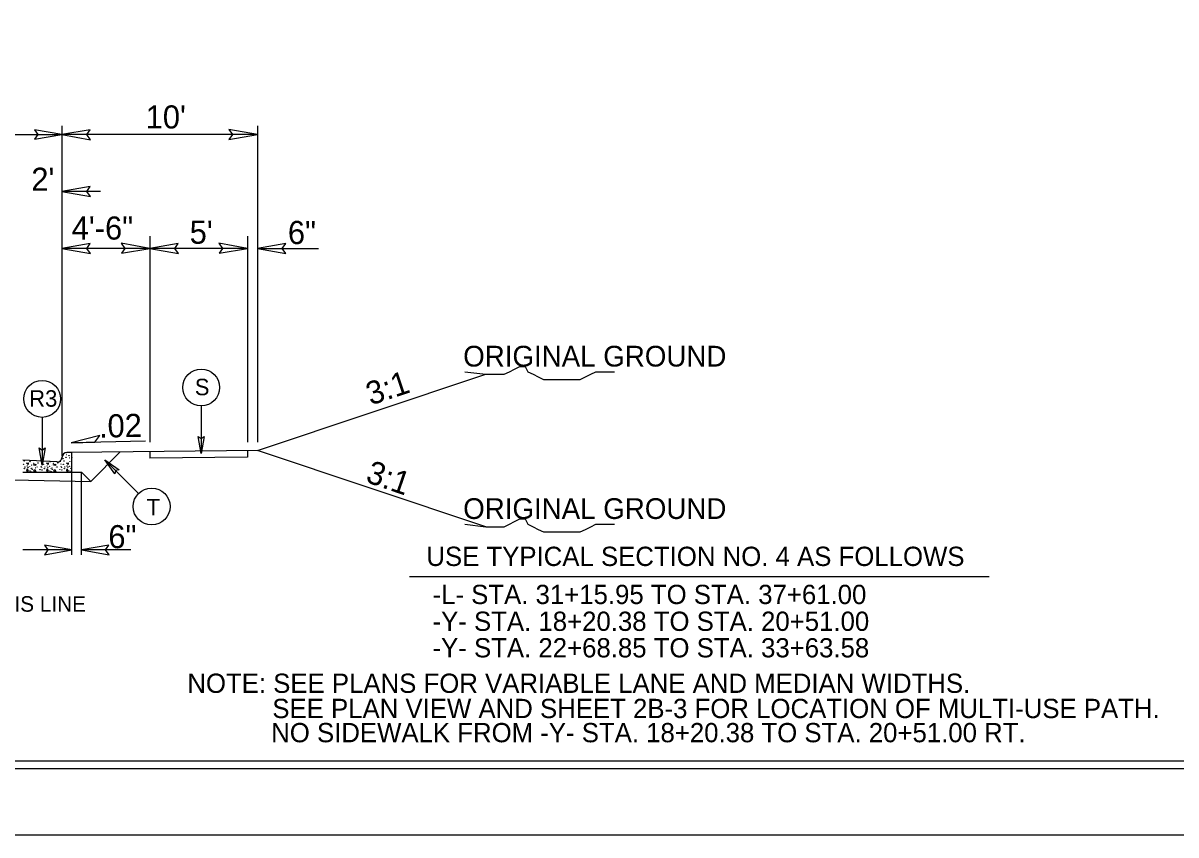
# Model space of a CAD drawing. Extents: x 958711 to 962106, y 831169 to 840840.
# Drawn here: x 959766.7 to 960156.3, y 838515.4 to 838789.5 of the extents above; entities that cross this region are included whole.
import ezdxf

# ---------------------------------------------------------------- set-up
doc = ezdxf.new("R2010")
doc.units = 0
for name, color, linetype in [('Old_Level_1', 7, 'Continuous'), ('Old_Level_11', 7, 'Continuous'), ('Old_Level_21', 7, 'Continuous'), ('Old_Level_3', 7, 'Continuous'), ('Prop Dimension Text', 7, 'Continuous'), ('Sheet Plot Border Inside CELL', 7, 'Continuous'), ('Sheet Plot Border Outside CELL', 7, 'Continuous'), ('Sheet Typical CELL', 7, 'Continuous'), ('Typical ID Circle CELL', 7, 'Continuous'), ('Typical Terminator CELL', 7, 'Continuous'), ('Typical Text ID Circle CELL', 7, 'Continuous')]:
    doc.layers.add(name, color=color, linetype=linetype)

msp = doc.modelspace()

# ---------------------------------------------------------------- linework, layer by layer
at = {"layer": 'Old_Level_1'}
for p, q in [((959779.86, 838754.86), (959779.86, 838643.28)), ((959845.9, 838754.86), (959845.9, 838648.04)), ((959213.41, 838751.85), (959779.86, 838751.85)), ((959845.9, 838751.85), (959779.86, 838751.85)), ((959792.92, 838732.63), (959779.86, 838732.63)), ((959809.57, 838717.61), (959809.57, 838648.04)), ((959842.59, 838717.61), (959842.59, 838648.04)), ((959809.57, 838713.44), (959779.86, 838713.44)), ((959842.59, 838713.44), (959809.57, 838713.44)), ((959845.9, 838713.44), (959866.56, 838713.44)), ((959845.9, 838645.18), (959923.08, 838670.91)), ((959808.08, 838648.31), (959782.97, 838647.81)), ((959845.9, 838645.18), (959782.93, 838644.55)), ((959789.59, 838634.78), (959799.52, 838644.71)), ((959809.57, 838644.81), (959809.57, 838642.63)), ((959842.59, 838645.14), (959842.59, 838642.97)), ((959923.08, 838619.45), (959845.9, 838645.18)), ((959842.59, 838642.97), (959809.57, 838642.63)), ((959653.23, 838637.54), (959789.59, 838634.78)), ((959783.22, 838637.91), (959786.52, 838637.85)), ((959783.22, 838610.01), (959783.22, 838637.91)), ((959786.52, 838637.85), (959789.59, 838634.78)), ((959786.52, 838610.01), (959786.52, 838637.85)), ((959783.22, 838611.6), (959766.62, 838611.6)), ((959803.12, 838611.6), (959786.52, 838611.6)), ((959897.26, 838602.68), (960093.2, 838602.68))]:
    msp.add_line(p, q, dxfattribs=at)
at = {"layer": 'Old_Level_11'}
for p, q in [((959792.71, 838650.23), (959782.97, 838647.81)), ((959782.97, 838647.81), (959790.98, 838647.97)), ((959790.98, 838647.97), (959792.71, 838650.23))]:
    msp.add_line(p, q, dxfattribs=at)
for points in [[(959789.46, 838753.51), (959779.86, 838751.85), (959789.53, 838750.13), (959788.3, 838751.85)], [(959836.29, 838750.19), (959845.9, 838751.85), (959836.24, 838753.56), (959837.46, 838751.85)], [(959789.46, 838734.28), (959779.86, 838732.63), (959789.53, 838730.91), (959788.3, 838732.63)], [(959789.46, 838715.1), (959779.86, 838713.44), (959789.53, 838711.72), (959788.3, 838713.44)], [(959799.97, 838711.79), (959809.57, 838713.44), (959799.91, 838715.15), (959801.14, 838713.44)], [(959819.18, 838715.1), (959809.57, 838713.44), (959819.24, 838711.72), (959818.01, 838713.44)], [(959832.99, 838711.79), (959842.59, 838713.44), (959832.93, 838715.15), (959834.16, 838713.44)], [(959855.5, 838715.1), (959845.9, 838713.44), (959855.56, 838711.72), (959854.33, 838713.44)]]:
    msp.add_lwpolyline(points, close=True, dxfattribs=at)
at = {"layer": 'Old_Level_21'}
for points in [[(959915.99, 838671.79), (959923.08, 838670.91), (959924.86, 838670.91), (959927.52, 838670.91), (959929.3, 838670.91), (959931.06, 838671.79), (959932.84, 838672.69), (959934.61, 838673.57), (959936.39, 838673.57), (959937.29, 838671.79), (959939.05, 838670.91), (959940.82, 838670.01), (959942.59, 838669.14), (959944.37, 838669.14), (959946.14, 838669.14), (959947.92, 838669.14), (959949.69, 838669.14), (959951.46, 838669.14), (959953.23, 838669.14), (959955.01, 838669.14), (959956.78, 838670.01), (959958.55, 838670.91), (959960.32, 838671.79), (959962.99, 838671.79), (959964.76, 838671.79), (959966.54, 838671.79)], [(959915.99, 838620.33), (959923.08, 838619.45), (959924.86, 838619.45), (959927.52, 838619.45), (959929.3, 838619.45), (959931.06, 838620.33), (959932.84, 838621.22), (959934.61, 838622.1), (959936.39, 838622.1), (959937.29, 838620.33), (959939.05, 838619.45), (959940.82, 838618.55), (959942.59, 838617.68), (959944.37, 838617.68), (959946.14, 838617.68), (959947.92, 838617.68), (959949.69, 838617.68), (959951.46, 838617.68), (959953.23, 838617.68), (959955.01, 838617.68), (959956.78, 838618.55), (959958.55, 838619.45), (959960.32, 838620.33), (959962.99, 838620.33), (959964.76, 838620.33), (959966.54, 838620.33)]]:
    msp.add_lwpolyline(points, dxfattribs=at)
at = {"layer": 'Old_Level_3'}
for p, q in [((959782.93, 838644.55), (959781.56, 838644.55)), ((959783.22, 838641.23), (959783.22, 838644.26)), ((959778.19, 838641.32), (959766.65, 838641.9)), ((959767.91, 838640.97), (959768.49, 838641)), ((959768.49, 838640.42), (959767.91, 838640.97)), ((959768.49, 838641), (959768.49, 838640.42)), ((959770.17, 838640.36), (959771, 838640.59)), ((959770.91, 838640.11), (959770.17, 838640.36)), ((959771, 838640.59), (959770.91, 838640.11)), ((959774.63, 838640.97), (959775.22, 838641)), ((959775.22, 838640.42), (959774.63, 838640.97)), ((959775.22, 838641), (959775.22, 838640.42)), ((959776.9, 838640.36), (959777.73, 838640.59)), ((959777.64, 838640.11), (959776.9, 838640.36)), ((959777.73, 838640.59), (959777.64, 838640.11)), ((959778.19, 838641.32), (959778.19, 838641.32)), ((959779.89, 838642.36), (959779.74, 838642.39)), ((959779.77, 838642.5), (959779.89, 838642.36)), ((959781.36, 838640.97), (959781.95, 838641)), ((959781.95, 838640.42), (959781.36, 838640.97)), ((959781.95, 838641), (959781.95, 838640.42)), ((959783.22, 838637.91), (959783.22, 838641.23)), ((959766.65, 838637.91), (959783.22, 838637.91)), ((959768.12, 838638.95), (959767.94, 838638.33)), ((959767.94, 838638.33), (959768.58, 838638.3)), ((959768.58, 838638.3), (959768.12, 838638.95)), ((959770.85, 838638.64), (959770.29, 838638.24)), ((959770.29, 838638.24), (959771.19, 838638.03)), ((959771.19, 838638.03), (959770.85, 838638.64)), ((959774.84, 838638.95), (959774.67, 838638.33)), ((959774.67, 838638.33), (959775.3, 838638.3)), ((959775.3, 838638.3), (959774.84, 838638.95)), ((959777.58, 838638.64), (959777.02, 838638.24)), ((959777.02, 838638.24), (959777.92, 838638.03)), ((959777.92, 838638.03), (959777.58, 838638.64)), ((959781.57, 838638.95), (959781.4, 838638.33)), ((959781.4, 838638.33), (959782.04, 838638.3)), ((959782.04, 838638.3), (959781.57, 838638.95))]:
    msp.add_line(p, q, dxfattribs=at)
for centre in [(959766.86, 838640.51), (959767.13, 838641.62), (959769.07, 838641.43), (959769.62, 838640.23), (959770.32, 838640.82), (959771.77, 838640.97), (959772.85, 838640.57), (959773.59, 838640.51), (959776.35, 838640.23), (959777.05, 838640.82), (959778.5, 838640.97), (959779.48, 838641.58), (959779.57, 838640.57), (959780.25, 838642.41), (959780.28, 838643.71), (959780.31, 838640.51), (959780.59, 838641.62), (959781.24, 838642.91), (959781.39, 838643.83), (959782.25, 838643.46), (959782.41, 838642.72), (959782.53, 838641.43), (959783.07, 838640.23), (959783.17, 838642.81), (959767.19, 838639.04), (959767.35, 838639.59), (959768.15, 838639.92), (959768.4, 838639.38), (959768.92, 838639.83), (959769.07, 838638.3), (959769.5, 838639.16), (959769.59, 838638.05), (959769.8, 838639.35), (959769.89, 838638.82), (959770.85, 838639.35), (959771.49, 838639.62), (959772.45, 838638.73), (959772.88, 838639.77), (959772.97, 838639.5), (959773.12, 838638.58), (959773.92, 838639.04), (959774.08, 838639.59), (959774.88, 838639.92), (959775.12, 838639.38), (959775.65, 838639.83), (959775.8, 838638.3), (959776.23, 838639.16), (959776.31, 838638.05), (959776.53, 838639.35), (959776.62, 838638.82), (959777.58, 838639.35), (959778.22, 838639.62), (959779.17, 838638.73), (959779.61, 838639.77), (959779.7, 838639.5), (959779.85, 838638.58), (959780.65, 838639.04), (959780.81, 838639.59), (959781.61, 838639.92), (959781.85, 838639.38), (959782.37, 838639.83), (959782.53, 838638.3), (959782.96, 838639.16), (959783.04, 838638.05)]:
    msp.add_circle(centre, 0.0432, dxfattribs=at)
for centre, radius, start, end in [((959781.56, 838642.89), 1.66, 90, 178.9266), ((959782.93, 838644.26), 0.287, 0, 90), ((959783.04, 838644.48), 0.0432, 169.6531, 280.3469), ((959772.75, 838641.58), 0.0432, 164.1199, 10.1626), ((959775.8, 838641.43), 0.0432, 162.062, 12.2205), ((959778.27, 838642.96), 1.64, 267.1376, 358.9266), ((959783.26, 838639.35), 0.0432, 150.4173, 209.5827)]:
    msp.add_arc(centre, radius, start, end, dxfattribs=at)
at = {"layer": 'Sheet Plot Border Inside CELL'}
msp.add_lwpolyline([(960390.3, 839592.94), (958723.8, 839592.94), (958723.8, 838537.84), (960390.3, 838537.84)], close=True, dxfattribs=at)
at = {"layer": 'Sheet Plot Border Outside CELL'}
msp.add_lwpolyline([(960394.8, 839615.39), (958710.8, 839615.39), (958710.8, 838515.39), (960394.8, 838515.39)], close=True, dxfattribs=at)
at = {"layer": 'Sheet Typical CELL'}
msp.add_lwpolyline([(960377.8, 839590.39), (958877.8, 839590.39), (958877.8, 838540.39), (960377.8, 838540.39)], close=True, dxfattribs=at)
at = {"layer": 'Typical ID Circle CELL'}
for p, q in [((959826.93, 838660.26), (959826.93, 838644.17)), ((959773.17, 838656.38), (959773.17, 838640.29)), ((959805.78, 838630.68), (959794.4, 838642.05))]:
    msp.add_line(p, q, dxfattribs=at)
for centre in [(959826.93, 838666.48), (959773.17, 838662.61), (959810.18, 838626.28)]:
    msp.add_circle(centre, 6.23, dxfattribs=at)
at = {"layer": 'Typical Terminator CELL'}
for points in [[(959770.63, 838750.26), (959779.86, 838751.85), (959770.58, 838753.49), (959771.76, 838751.85)], [(959827.92, 838649.93), (959826.93, 838644.17), (959825.9, 838649.97), (959826.93, 838649.23)], [(959774.16, 838646.06), (959773.17, 838640.29), (959772.15, 838646.09), (959773.17, 838645.35)], [(959797.78, 838637.28), (959794.4, 838642.05), (959799.23, 838638.68), (959797.98, 838638.48)], [(959774, 838610.01), (959783.22, 838611.6), (959773.95, 838613.24), (959775.13, 838611.6)], [(959795.75, 838613.19), (959786.52, 838611.6), (959795.8, 838609.96), (959794.62, 838611.6)]]:
    msp.add_lwpolyline(points, close=True, dxfattribs=at)

# ---------------------------------------------------------------- texts
at = {"layer": 'Old_Level_1'}
for s, height, p in [('USE TYPICAL SECTION NO. 4 AS FOLLOWS', 6.5088, (959903, 838606.2)), ('-L- STA. 31+15.95 TO STA. 37+61.00', 6.5088, (959905.09, 838593.34)), ('GRADE TO THIS LINE', 5.2473, (959715.87, 838590.76)), ('-Y- STA. 18+20.38 TO STA. 20+51.00', 6.5088, (959905.09, 838584.28)), ('-Y- STA. 22+68.85 TO STA. 33+63.58', 6.5088, (959905.09, 838575.33)), ('NOTE: SEE PLANS FOR VARIABLE LANE AND MEDIAN WIDTHS.', 6.5088, (959822.24, 838563.35)), ('SEE PLAN VIEW AND SHEET 2B-3 FOR LOCATION OF MULTI-USE PATH.', 6.5088, (959850.96, 838554.84)), ('NO SIDEWALK FROM -Y- STA. 18+20.38 TO STA. 20+51.00 RT.', 6.5088, (959850.58, 838546.68))]:
    msp.add_text(s, height=height, dxfattribs=at).set_placement(p)
at = {"layer": 'Old_Level_21'}
for p in [(959915.45, 838673.54), (959915.45, 838622.08)]:
    msp.add_text('ORIGINAL GROUND', height=7, dxfattribs=at).set_placement(p)
at = {"layer": 'Old_Level_3'}
for s, p in [("10'", (959808.16, 838753.92)), ("2'", (959769.52, 838732.87)), ('4\'-6"', (959783.16, 838716.41)), ("5'", (959823.03, 838715)), ('6"', (959856.21, 838714.91))]:
    msp.add_text(s, height=7.801, dxfattribs=at).set_placement(p)
for rotation, p in [(18.4348, (959884.2, 838660.36)), (341.0454, (959882.14, 838634.67))]:
    msp.add_text('3:1', height=7.801, rotation=rotation, dxfattribs=at).set_placement(p)
at = {"layer": 'Prop Dimension Text'}
for s, rotation, p in [('.02', 1.1839, (959792.46, 838649.51)), ('6"', 0, (959795.55, 838612.2))]:
    msp.add_text(s, height=7.801, rotation=rotation, dxfattribs=at).set_placement(p)
at = {"layer": 'Typical Text ID Circle CELL'}
for s, height, p in [('S', 5.57, (959824.76, 838663.85)), ('R3', 5.572, (959768.79, 838659.98)), ('T', 5.57, (959808.47, 838623.3))]:
    msp.add_text(s, height=height, dxfattribs=at).set_placement(p)

doc.saveas('drawing.dxf')
